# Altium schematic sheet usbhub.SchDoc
size 431 x 279 mm; Date: Not shown in title block; ApprovedBy: Not shown in title block; CheckedBy: Not shown in title block; Author: Not shown in title block; CompanyName: Not shown in title block; Engineer: Not shown in title block; Organization: Not shown in title block; Address1: Not shown in title block; Address2: Not shown in title block; Address3: Not shown in title block; Address4: Not shown in title block; DocumentNumber: 2; Revision: Use project parameter SCH_Rev; SheetNumber: 2; SheetTotal: 6; PageSetup: Record=PageOptions¦CenterHorizontal=True¦CenterVertical=True¦PrintScale=1.00¦XCorrection=1.00¦YCorrection=1.00¦PrintKind=0¦BorderSize=5000000¦LeftOffset=0¦BottomOffset=0¦Orientation=2¦PaperLength=1000¦PaperWidth=1000¦Scale=100¦PaperSource=15¦PrintQuality=600¦MediaType=1¦DitherType=10¦PaperKind=Letter¦PrintScaleMode=1
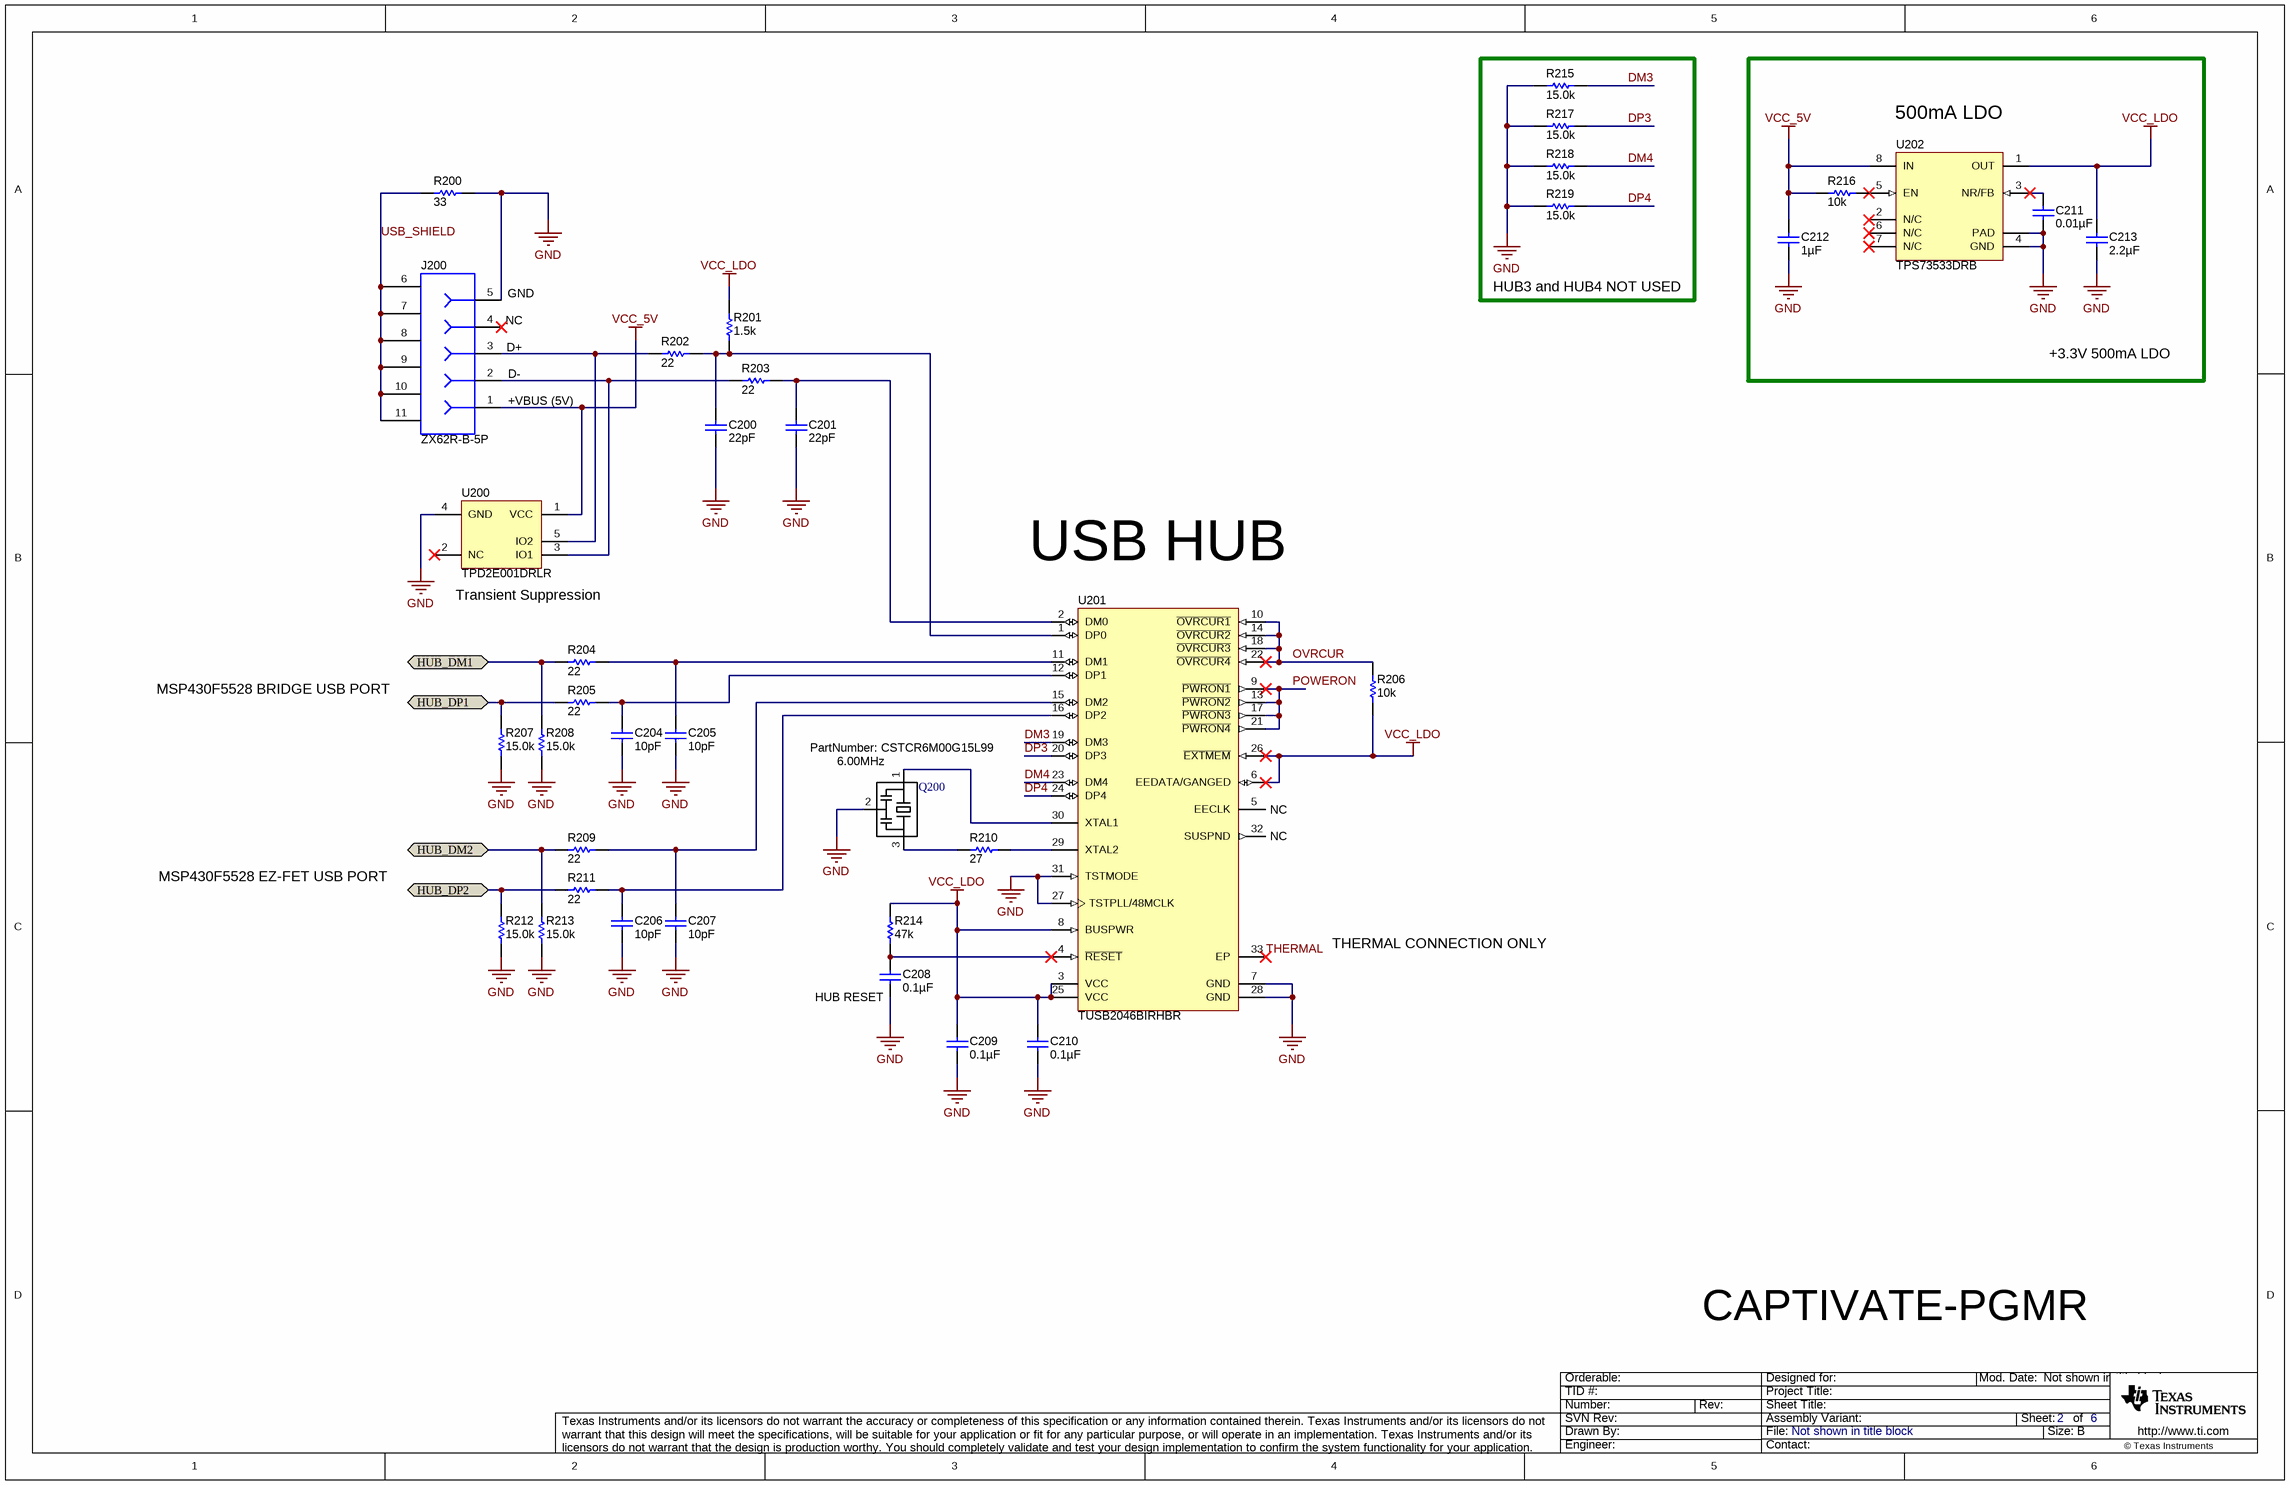
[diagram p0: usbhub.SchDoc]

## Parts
C200  ValueDisplayed: 22pF  [0402]  (hidden comment: GRM1555C1H220JA01D)
C201  ValueDisplayed: 22pF  [0402]  (hidden comment: GRM1555C1H220JA01D)
C204  ValueDisplayed: 10pF  [0402]  (hidden comment: GRM1555C1H100JA01D)
C205  ValueDisplayed: 10pF  [0402]  (hidden comment: GRM1555C1H100JA01D)
C206  ValueDisplayed: 10pF  [0402]  (hidden comment: GRM1555C1H100JA01D)
C207  ValueDisplayed: 10pF  [0402]  (hidden comment: GRM1555C1H100JA01D)
C208  ValueDisplayed: 0.1µF  [0402]  (hidden comment: GRM155R61C104KA88D)
C209  ValueDisplayed: 0.1µF  [0402]  (hidden comment: GRM155R61C104KA88D)
C210  ValueDisplayed: 0.1µF  [0402]  (hidden comment: GRM155R61C104KA88D)
C211  ValueDisplayed: 0.01µF  [0402]  (hidden comment: GRM155R61C103KA01D)
C212  ValueDisplayed: 1µF  [0603]  (hidden comment: C0603C105K8PACTU)
C213  ValueDisplayed: 2.2µF  [0603]  (hidden comment: C0603C225K8PACTU)
J200  ZX62R-B-5P  [CONN_USB_micro_ZX62R-B-5PA]
Q200  Value Displayed: 6.00MHz  PartNumber: CSTCR6M00G15L99  [CSTCR CERAMIC RESONATOR - MURATA]
R200  value 33  [0402]  (hidden comment: CRCW040233R0JNED)
R201  value 1.5k  [0402]  (hidden comment: CRCW04021K50JNED)
R202  value 22  [0402]  (hidden comment: CRCW040222R0JNED)
R203  value 22  [0402]  (hidden comment: CRCW040222R0JNED)
R204  value 22  [0402]  (hidden comment: CRCW040222R0JNED)
R205  value 22  [0402]  (hidden comment: CRCW040222R0JNED)
R206  ValueDisplayed: 10k  [0402]  (hidden comment: CRCW040210K0JNED)
R207  value 15.0k  [0402]  (hidden comment: CRCW040215K0FKED)
R208  value 15.0k  [0402]  (hidden comment: CRCW040215K0FKED)
R209  value 22  [0402]  (hidden comment: CRCW040222R0JNED)
R210  value 27  [0402]  (hidden comment: CRCW040227R0JNED)
R211  value 22  [0402]  (hidden comment: CRCW040222R0JNED)
R212  value 15.0k  [0402]  (hidden comment: CRCW040215K0FKED)
R213  value 15.0k  [0402]  (hidden comment: CRCW040215K0FKED)
R214  value 47k  [0402]  (hidden comment: CRCW040247K0JNED)
R215  value 15.0k  [0402]  (hidden comment: CRCW040215K0FKED)
R216  value 10k  [0402]  (hidden comment: CRCW040210K0JNED)
R217  value 15.0k  [0402]  (hidden comment: CRCW040215K0FKED)
R218  value 15.0k  [0402]  (hidden comment: CRCW040215K0FKED)
R219  value 15.0k  [0402]  (hidden comment: CRCW040215K0FKED)
U200  TPD2E001DRLR  [DRL0005A]
U201  TUSB2046BIRHBR  [RHB0032E]
U202  TPS73533DRB  [DRB0008A]

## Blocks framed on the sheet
HUB3 and HUB4 NOT USED: R215 R217-R219
500mA LDO: C211-C213 R216 U202

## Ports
HUB_DM1 (bidir), HUB_DM2 (bidir), HUB_DP1 (bidir), HUB_DP2 (bidir)

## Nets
GND: C200.2 C201.2 C204.2 C205.2 C206.2 C207.2 C208.2 C209.2 C210.2 C211.2 C212.2 C213.2 J200.5 Q200.2 R200.2 R207.1 R208.1 R212.1 R213.1 R215.1 R217.1 R218.1 R219.1 U200.4(GND) U201.7(GND) U201.27(TSTPLL/48MCLK) U201.28(GND) U201.31(TSTMODE) U202.4(GND) U202.9(PAD)
VCC_5V: C212.1 J200.1 R216.1 U200.1(VCC) U202.8(IN)
VCC_LDO: C209.1 C210.1 C213.1 R201.2 R206.1 R214.2 U201.3(VCC) U201.6(EEDATA/GANGED) U201.8(BUSPWR) U201.25(VCC) U201.26(~{EXTMEM}) U202.1(OUT)
DM3: R215.2 U201.19(DM3)
DM4: R218.2 U201.23(DM4)
DP3: R217.2 U201.20(DP3)
DP4: R219.2 U201.24(DP4)
HUB_DM1: R204.1 R208.2 ; port HUB_DM1
HUB_DM2: R209.1 R213.2 ; port HUB_DM2
HUB_DP1: R205.1 R207.2 ; port HUB_DP1
HUB_DP2: R211.1 R212.2 ; port HUB_DP2
OVRCUR: R206.2 U201.10(~{OVRCUR1}) U201.14(~{OVRCUR2}) U201.18(~{OVRCUR3}) U201.22(~{OVRCUR4})
POWERON: U201.9(~{PWRON1}) U201.13(~{PWRON2}) U201.17(~{PWRON3}) U201.21(~{PWRON4})
THERMAL: U201.33(EP)
USB_SHIELD: J200.6 J200.7 J200.8 J200.9 J200.10 J200.11 R200.1
NetC200_1: C200.1 R201.1 R202.2 U201.1(DP0)
NetC201_1: C201.1 R203.2 U201.2(DM0)
NetC204_1: C204.1 R205.2 U201.12(DP1)
NetC205_1: C205.1 R204.2 U201.11(DM1)
NetC206_1: C206.1 R211.2 U201.16(DP2)
NetC207_1: C207.1 R209.2 U201.15(DM2)
NetC208_1: C208.1 R214.1 U201.4(~{RESET})
NetC211_1: C211.1 U202.3(NR/FB)
NetJ200_2: J200.2 R203.1 U200.3(IO1)
NetJ200_3: J200.3 R202.1 U200.5(IO2)
NetQ200_1: Q200.1 U201.30(XTAL1)
NetQ200_3: Q200.3 R210.1
NetR210_2: R210.2 U201.29(XTAL2)
NetR216_2: R216.2 U202.5(EN)

Not connected (* = marked no-connect by the designer): J200 4*; U200 2(NC)*; U201 5(EECLK) 32(SUSPND); U202 2(N/C)* 6(N/C)* 7(N/C)*

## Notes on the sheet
- (near J200) GND
- (near J200) NC
- (near J200) D+
- +3.3V 500mA LDO
- (near J200) D-
- (near J200) +VBUS (5V)
- (near U201) USB HUB
- (near U200) Transient Suppression
- MSP430F5528 BRIDGE USB PORT
- (near U201) NC
- MSP430F5528 EZ-FET USB PORT
- THERMAL CONNECTION ONLY
- (near C208) HUB RESET
- CAPTIVATE-PGMR

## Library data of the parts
C200 C201 = GRM1555C1H220JA01D: CAP, CERM, 22pF, 50V, +/-5%, C0G/NP0, 0402; Manufacturer: MuRata; Polarized: N; CompType: Capacitor; U/M: EA; Cap_F: 0.000000000022; Tolerance_%: 5; Value1: Unknown; VDC_V: 50; TaMin_C: -55; TaMax_C: 125
C204-C207 = GRM1555C1H100JA01D: CAP, CERM, 10pF, 50V, +/-5%, C0G/NP0, 0402; Manufacturer: MuRata; Polarized: N; CompType: Capacitor; U/M: EA; Cap_F: 0.00000000001; Tolerance_%: 5; Value1: Unknown; VDC_V: 50; TaMin_C: -55; TaMax_C: 125
C208-C210 = GRM155R61C104KA88D: CAP, CERM, 0.1uF, 16V, +/-10%, X5R, 0402; Manufacturer: MuRata; Polarized: N; CompType: Capacitor; U/M: EA; Cap_F: 0.0000001; Tolerance_%: 10; Value1: Unknown; VDC_V: 16; TaMin_C: -55; TaMax_C: 85
C211 = GRM155R61C103KA01D: CAP, CERM, 0.01uF, 16V, +/-10%, X5R, 0402; Manufacturer: MuRata; Polarized: N; CompType: Capacitor; U/M: EA; Cap_F: 0.00000001; Tolerance_%: 10; Value1: Unknown; VDC_V: 16; TaMin_C: -55; TaMax_C: 85
C212 = C0603C105K8PACTU: CAP, CERM, 1uF, 10V, +/-10%, X5R, 0603; Manufacturer: Kemet; Polarized: N; CompType: Capacitor; U/M: EA; Cap_F: 0.000001; Tolerance_%: 10; Value1: Unknown; TaMin_C: -55; TaMax_C: 85
C213 = C0603C225K8PACTU: CAP, CERM, 2.2uF, 10V, +/-10%, X5R, 0603; Manufacturer: Kemet; Polarized: N; CompType: Capacitor; U/M: EA; Cap_F: 0.0000022; Tolerance_%: 10; Value1: Unknown; TaMin_C: -55; TaMax_C: 85
J200 = ZX62R-B-5P: Connector, micro USB Type B, Reverse, Receptacle, SMD; Manufacturer: Hirose Electric Co. Ltd.; SymbolCreator: a0411947; U/M: EA
Q200 = MURATA-FILTER_CSTCR6M00G15: 6.00MHz resonator
R200 = CRCW040233R0JNED: RES, 33 ohm, 5%, 0.063W, 0402; Manufacturer: Vishay-Dale; CompType: Resistor; Value_Code: 33R0; Tolerance_%: 5; Power_W: 0.063; VDC_V: 50; TempCo: 200 ppm/C; EIA_Code: E24; U/M: EA
R201 = CRCW04021K50JNED: RES, 1.5k ohm, 5%, 0.063W, 0402; Manufacturer: Vishay-Dale; CompType: Resistor; Res_ohm: 1500; Value_Code: 1k50; Tolerance_%: 5; Power_W: 0.063; VDC_V: 50; TempCo: 200 ppm/C; EIA_Code: E24; U/M: EA
R202-R205 R209 R211 = CRCW040222R0JNED: RES, 22 ohm, 5%, 0.063W, 0402; Manufacturer: Vishay-Dale; CompType: Resistor; Value_Code: 22R0; Tolerance_%: 5; Power_W: 0.063; VDC_V: 50; TempCo: 200 ppm/C; EIA_Code: E24; U/M: EA
R206 = CRCW040210K0JNED: RES, 10 k, 5%, 0.063 W, 0402; Manufacturer: Vishay-Dale; CompType: Resistor; Value: 10k; Res_ohm: 10000; Value_Code: 10k0; Tolerance_%: 5; Power_W: 0.063; Value2: 0.063W; VDC_V: 50; TempCo: 200 ppm/C; EIA_Code: E24; U/M: EA
R207 R208 R212 R213 R215 R217-R219 = CRCW040215K0FKED: RES, 15.0k ohm, 1%, 0.063W, 0402; Manufacturer: Vishay-Dale; CompType: Resistor; Res_ohm: 15000; Value_Code: 15k0; Tolerance_%: 1; Power_W: 0.063; VDC_V: 50; TempCo: 100 ppm/C; EIA_Code: E96; U/M: EA
R210 = CRCW040227R0JNED: RES, 27 ohm, 5%, 0.063W, 0402; Manufacturer: Vishay-Dale; CompType: Resistor; Value_Code: 27R0; Tolerance_%: 5; Power_W: 0.063; VDC_V: 50; TempCo: 200 ppm/C; EIA_Code: E24; U/M: EA
R214 = CRCW040247K0JNED: RES, 47k ohm, 5%, 0.063W, 0402; Manufacturer: Vishay-Dale; CompType: Resistor; Res_ohm: 47000; Value_Code: 47k0; Tolerance_%: 5; Power_W: 0.063; VDC_V: 50; TempCo: 200 ppm/C; EIA_Code: E24; U/M: EA
R216 = CRCW040210K0JNED: RES, 10k ohm, 5%, 0.063W, 0402; Manufacturer: Vishay-Dale; CompType: Resistor; Res_ohm: 10000; Value_Code: 10k0; Tolerance_%: 5; Power_W: 0.063; VDC_V: 50; TempCo: 200 ppm/C; EIA_Code: E24; U/M: EA
U200 = TPD2E001DRLR: Low-Capacitance + / - 15 kV ESD-Protection Array for High-Speed Data Interfaces, 2 Channels, -40 to +85 degC, 5-pin SOT (DRL), Green (RoHS & no Sb/Br); Manufacturer: Texas Instruments; Alternate Manufacturer: None; Alternate PartNumber: Equivalent; Breakdown Voltage(Min)(V): 11; IEC 61000-4-2 Air-Gap(+/- kV): 15; IEC 61000-4-2 Contact(+/- kV): 8; IO Capacitance(Typ)(pF): 1.5; IO Leakage Current(nA): 1; SubFamily: ESD Solution; USB High Speed: TRUE
U201 = TUSB2046BIRHBR: 4-Port Full-Speed USB Hub, 3.3V, -40 to 85 degC, 32-Pin QFN (RHB), Green (RoHS & no Sb/Br); Manufacturer: Texas Instruments; Alternate Manufacturer: None; Alternate PartNumber: Equivalent; SubFamily: USB Hub Controller; USB Speed: Full; USB Full Speed: True; Supply Voltage(s)(V): 3.3
U202 = TPS73533DRB: 500mA, Low Quiescent Current, Ultra-Low Noise, High PSRR Low-Dropout Linear Regulator, DRB0008A; Alternate Manufacturer: None; Manufacturer: Texas Instruments; SymbolCreator: a0411947; CompType: IC; U/M: EA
